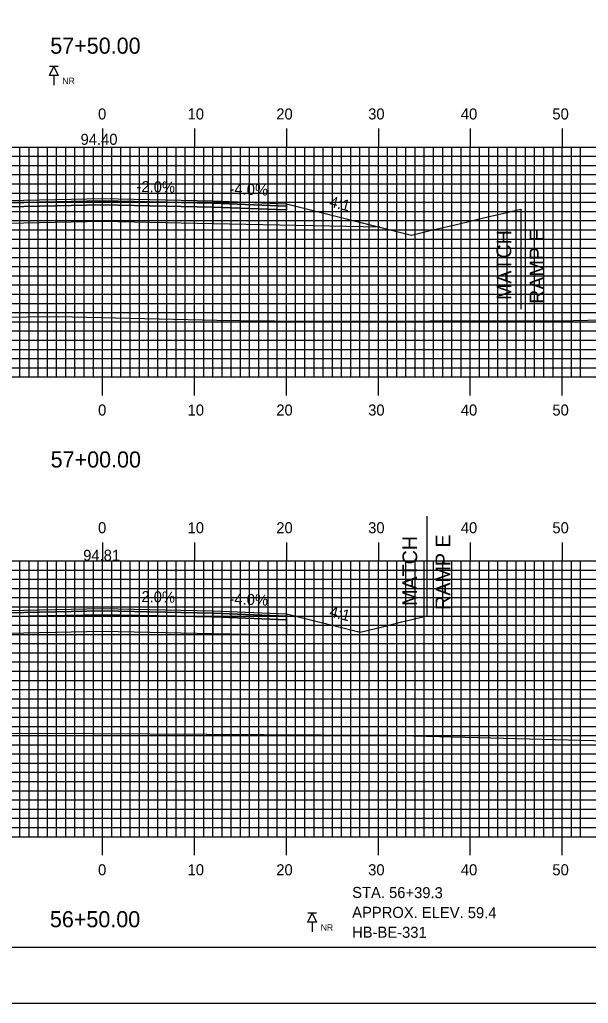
# Model space of a CAD drawing. Extents: x 1757069 to 1757412, y 442591 to 442811.
# Drawn here: x 1757225.6 to 1757287.4, y 442590.5 to 442697.5 of the extents above; entities that cross this region are included whole.
import ezdxf

# ---------------------------------------------------------------- set-up
doc = ezdxf.new("R2010")
doc.units = 0
for name, color, linetype in [('ANNOTATION', 7, 'Continuous'), ('BORDER', 7, 'Continuous'), ('BORING - NO REFUSAL', 7, 'Continuous'), ('D_Roadway_Centerline', 7, 'Continuous'), ('D_Roadway_Centerline_Text', 7, 'Continuous'), ('D_Roadway_Edge_Shoulder', 7, 'Continuous'), ('D_Roadway_Edge_TW', 7, 'Continuous'), ('D_Roadway_Pavement', 7, 'Continuous'), ('D_Roadway_SlopeLines', 7, 'Continuous'), ('D_Roadway_SubGrade', 7, 'Continuous'), ('H_V ANNOTATION', 7, 'Continuous'), ('MAJOR', 7, 'Continuous'), ('MINOR', 7, 'Continuous'), ('PLOT BOUNDARY', 7, 'Continuous'), ('S_Roadway_Centerline', 7, 'Continuous')]:
    doc.layers.add(name, color=color, linetype=linetype)

msp = doc.modelspace()

# ---------------------------------------------------------------- linework, layer by layer
at = {"layer": 'BORDER'}
msp.add_lwpolyline([(1757085, 442596.67), (1757405, 442596.67), (1757405, 442806.67), (1757085, 442806.67)], close=True, dxfattribs=at)
at = {"layer": 'BORING - NO REFUSAL'}
for p, q in [((1757229.78, 442692.42), (1757228.82, 442692.42)), ((1757229.3, 442691.46), (1757229.3, 442690.4)), ((1757257.88, 442600.35), (1757256.92, 442600.35)), ((1757257.4, 442599.39), (1757257.4, 442598.33))]:
    msp.add_line(p, q, dxfattribs=at)
for points in [[(1757229.3, 442692.42), (1757229.78, 442691.46), (1757228.82, 442691.46)], [(1757257.4, 442600.35), (1757257.88, 442599.39), (1757256.92, 442599.39)]]:
    msp.add_lwpolyline(points, close=True, dxfattribs=at)
at = {"layer": 'D_Roadway_Centerline'}
for points in [[(1757150.87, 442664.43), (1757178.46, 442673.58), (1757184.75, 442675.67), (1757187.19, 442676.48), (1757189.25, 442676.57), (1757189.96, 442676.6), (1757190.2, 442676.61), (1757193.88, 442676.78), (1757197.78, 442676.96), (1757197.9, 442676.96), (1757198.24, 442676.98), (1757200.33, 442677.07), (1757200.77, 442677.09), (1757206.86, 442677.37), (1757210.69, 442677.54), (1757212.29, 442677.62), (1757222.6, 442677.82), (1757234.6, 442678.06), (1757246.6, 442677.82), (1757254.6, 442677.5), (1757264.77, 442674.96), (1757268.22, 442674.1)], [(1757268.22, 442674.1), (1757270.53, 442674.65), (1757273.09, 442675.25), (1757274.59, 442675.61), (1757276.05, 442675.96), (1757278.57, 442676.55), (1757278.61, 442676.56), (1757278.62, 442676.56), (1757279.01, 442676.66), (1757280.11, 442676.92)], [(1757145.44, 442619.42), (1757182.82, 442631.81), (1757185.83, 442631.94), (1757187.53, 442632.02), (1757188.24, 442632.05), (1757193.86, 442632.31), (1757195.47, 442632.38), (1757196.4, 442632.42), (1757197.69, 442632.48), (1757201.15, 442632.63), (1757202.27, 442632.68), (1757203.92, 442632.76), (1757207.91, 442632.94), (1757222.6, 442633.23), (1757234.6, 442633.47), (1757246.6, 442633.23), (1757254.6, 442632.91), (1757262.62, 442630.91)], [(1757262.62, 442630.91), (1757265.21, 442631.54), (1757267.17, 442632.03), (1757267.79, 442632.18), (1757269.87, 442632.69)]]:
    msp.add_lwpolyline(points, dxfattribs=at)
at = {"layer": 'D_Roadway_Edge_Shoulder'}
for points in [[(1757246.6, 442677.82), (1757254.6, 442677.5), (1757254.6, 442677.25), (1757246.6, 442677.57)], [(1757246.6, 442633.23), (1757254.6, 442632.91), (1757254.6, 442632.66), (1757246.6, 442632.98)]]:
    msp.add_lwpolyline(points, close=True, dxfattribs=at)
at = {"layer": 'D_Roadway_Edge_TW'}
for points in [[(1757222.6, 442677.57), (1757222.6, 442677.82), (1757234.6, 442678.06), (1757246.6, 442677.82), (1757246.6, 442677.57), (1757234.6, 442677.81)], [(1757222.6, 442632.98), (1757222.6, 442633.23), (1757234.6, 442633.47), (1757246.6, 442633.23), (1757246.6, 442632.98), (1757234.6, 442633.22)]]:
    msp.add_lwpolyline(points, close=True, dxfattribs=at)
at = {"layer": 'D_Roadway_Pavement'}
for points in [[(1757222.6, 442677.15), (1757222.6, 442677.57), (1757234.6, 442677.81), (1757246.6, 442677.57), (1757246.6, 442677.15), (1757234.6, 442677.39)], [(1757246.6, 442677.57), (1757254.6, 442677.25), (1757254.6, 442676.83), (1757246.6, 442677.15)], [(1757222.6, 442632.57), (1757222.6, 442632.98), (1757234.6, 442633.22), (1757246.6, 442632.98), (1757246.6, 442632.57), (1757234.6, 442632.81)], [(1757246.6, 442632.98), (1757254.6, 442632.66), (1757254.6, 442632.25), (1757246.6, 442632.57)]]:
    msp.add_lwpolyline(points, close=True, dxfattribs=at)
at = {"layer": 'D_Roadway_SlopeLines'}
for points in [[(1757254.6, 442677.5), (1757268.22, 442674.1)], [(1757254.6, 442632.91), (1757262.62, 442630.91)]]:
    msp.add_lwpolyline(points, dxfattribs=at)
at = {"layer": 'D_Roadway_SubGrade'}
for p, q in [((1757280.11, 442676.92), (1757280.11, 442666.04)), ((1757269.87, 442643.52), (1757269.87, 442632.69))]:
    msp.add_line(p, q, dxfattribs=at)
for points in [[(1757222.6, 442675.32), (1757222.6, 442677.15), (1757234.6, 442677.39), (1757246.6, 442677.15), (1757246.6, 442675.32), (1757234.6, 442675.56)], [(1757246.6, 442677.15), (1757254.6, 442676.83), (1757254.6, 442677.25), (1757254.6, 442677.5), (1757264.77, 442674.96), (1757246.6, 442675.32)], [(1757222.6, 442630.73), (1757222.6, 442632.57), (1757234.6, 442632.81), (1757246.6, 442632.57), (1757246.6, 442630.73), (1757234.6, 442630.97)], [(1757246.6, 442632.57), (1757254.6, 442632.25), (1757254.6, 442632.66), (1757254.6, 442632.91), (1757254.6, 442630.57), (1757246.6, 442630.73)]]:
    msp.add_lwpolyline(points, close=True, dxfattribs=at)
at = {"layer": 'MAJOR'}
for p, q in [((1757234.6, 442685.67), (1757234.6, 442683.67)), ((1757244.6, 442685.67), (1757244.6, 442683.67)), ((1757254.6, 442685.67), (1757254.6, 442683.67)), ((1757264.6, 442685.67), (1757264.6, 442683.67)), ((1757274.6, 442685.67), (1757274.6, 442683.67)), ((1757284.6, 442685.67), (1757284.6, 442683.67)), ((1757094.6, 442683.67), (1757374.6, 442683.67)), ((1757094.6, 442683.67), (1757374.6, 442683.67)), ((1757234.6, 442658.67), (1757234.6, 442683.67)), ((1757244.6, 442658.67), (1757244.6, 442683.67)), ((1757254.6, 442658.67), (1757254.6, 442683.67)), ((1757264.6, 442658.67), (1757264.6, 442683.67)), ((1757274.6, 442658.67), (1757274.6, 442683.67)), ((1757284.6, 442658.67), (1757284.6, 442683.67)), ((1757094.6, 442678.67), (1757374.6, 442678.67)), ((1757094.6, 442673.67), (1757374.6, 442673.67)), ((1757094.6, 442668.67), (1757374.6, 442668.67)), ((1757094.6, 442663.67), (1757374.6, 442663.67)), ((1757094.6, 442658.67), (1757374.6, 442658.67)), ((1757094.6, 442658.67), (1757374.6, 442658.67)), ((1757234.6, 442656.66), (1757234.6, 442658.67)), ((1757244.6, 442656.66), (1757244.6, 442658.67)), ((1757254.6, 442656.66), (1757254.6, 442658.67)), ((1757264.6, 442656.66), (1757264.6, 442658.67)), ((1757274.6, 442656.66), (1757274.6, 442658.67)), ((1757284.6, 442656.66), (1757284.6, 442658.67)), ((1757234.6, 442640.67), (1757234.6, 442638.67)), ((1757244.6, 442640.67), (1757244.6, 442638.67)), ((1757254.6, 442640.67), (1757254.6, 442638.67)), ((1757264.6, 442640.67), (1757264.6, 442638.67)), ((1757274.6, 442640.67), (1757274.6, 442638.67)), ((1757284.6, 442640.67), (1757284.6, 442638.67)), ((1757094.6, 442638.67), (1757374.6, 442638.67)), ((1757094.6, 442638.67), (1757374.6, 442638.67)), ((1757234.6, 442608.67), (1757234.6, 442638.67)), ((1757244.6, 442608.67), (1757244.6, 442638.67)), ((1757254.6, 442608.67), (1757254.6, 442638.67)), ((1757264.6, 442608.67), (1757264.6, 442638.67)), ((1757274.6, 442608.67), (1757274.6, 442638.67)), ((1757284.6, 442608.67), (1757284.6, 442638.67)), ((1757094.6, 442633.67), (1757374.6, 442633.67)), ((1757094.6, 442628.67), (1757374.6, 442628.67)), ((1757094.6, 442623.67), (1757374.6, 442623.67)), ((1757094.6, 442618.67), (1757374.6, 442618.67)), ((1757094.6, 442613.67), (1757374.6, 442613.67)), ((1757094.6, 442608.67), (1757374.6, 442608.67)), ((1757094.6, 442608.67), (1757374.6, 442608.67)), ((1757234.6, 442606.66), (1757234.6, 442608.67)), ((1757244.6, 442606.66), (1757244.6, 442608.67)), ((1757254.6, 442606.66), (1757254.6, 442608.67)), ((1757264.6, 442606.66), (1757264.6, 442608.67)), ((1757274.6, 442606.66), (1757274.6, 442608.67)), ((1757284.6, 442606.66), (1757284.6, 442608.67))]:
    msp.add_line(p, q, dxfattribs=at)
at = {"layer": 'MINOR'}
for p, q in [((1757225.6, 442658.67), (1757225.6, 442683.67)), ((1757226.6, 442658.67), (1757226.6, 442683.67)), ((1757227.6, 442658.67), (1757227.6, 442683.67)), ((1757228.6, 442658.67), (1757228.6, 442683.67)), ((1757229.6, 442658.67), (1757229.6, 442683.67)), ((1757230.6, 442658.67), (1757230.6, 442683.67)), ((1757231.6, 442658.67), (1757231.6, 442683.67)), ((1757232.6, 442658.67), (1757232.6, 442683.67)), ((1757233.6, 442658.67), (1757233.6, 442683.67)), ((1757235.6, 442658.67), (1757235.6, 442683.67)), ((1757236.6, 442658.67), (1757236.6, 442683.67)), ((1757237.6, 442658.67), (1757237.6, 442683.67)), ((1757238.6, 442658.67), (1757238.6, 442683.67)), ((1757239.6, 442658.67), (1757239.6, 442683.67)), ((1757240.6, 442658.67), (1757240.6, 442683.67)), ((1757241.6, 442658.67), (1757241.6, 442683.67)), ((1757242.6, 442658.67), (1757242.6, 442683.67)), ((1757243.6, 442658.67), (1757243.6, 442683.67)), ((1757245.6, 442658.67), (1757245.6, 442683.67)), ((1757246.6, 442658.67), (1757246.6, 442683.67)), ((1757247.6, 442658.67), (1757247.6, 442683.67)), ((1757248.6, 442658.67), (1757248.6, 442683.67)), ((1757249.6, 442658.67), (1757249.6, 442683.67)), ((1757250.6, 442658.67), (1757250.6, 442683.67)), ((1757251.6, 442658.67), (1757251.6, 442683.67)), ((1757252.6, 442658.67), (1757252.6, 442683.67)), ((1757253.6, 442658.67), (1757253.6, 442683.67)), ((1757255.6, 442658.67), (1757255.6, 442683.67)), ((1757256.6, 442658.67), (1757256.6, 442683.67)), ((1757257.6, 442658.67), (1757257.6, 442683.67)), ((1757258.6, 442658.67), (1757258.6, 442683.67)), ((1757259.6, 442658.67), (1757259.6, 442683.67)), ((1757260.6, 442658.67), (1757260.6, 442683.67)), ((1757261.6, 442658.67), (1757261.6, 442683.67)), ((1757262.6, 442658.67), (1757262.6, 442683.67)), ((1757263.6, 442658.67), (1757263.6, 442683.67)), ((1757265.6, 442658.67), (1757265.6, 442683.67)), ((1757266.6, 442658.67), (1757266.6, 442683.67)), ((1757267.6, 442658.67), (1757267.6, 442683.67)), ((1757268.6, 442658.67), (1757268.6, 442683.67)), ((1757269.6, 442658.67), (1757269.6, 442683.67)), ((1757270.6, 442658.67), (1757270.6, 442683.67)), ((1757271.6, 442658.67), (1757271.6, 442683.67)), ((1757272.6, 442658.67), (1757272.6, 442683.67)), ((1757273.6, 442658.67), (1757273.6, 442683.67)), ((1757275.6, 442658.67), (1757275.6, 442683.67)), ((1757276.6, 442658.67), (1757276.6, 442683.67)), ((1757277.6, 442658.67), (1757277.6, 442683.67)), ((1757278.6, 442658.67), (1757278.6, 442683.67)), ((1757279.6, 442658.67), (1757279.6, 442683.67)), ((1757280.6, 442658.67), (1757280.6, 442683.67)), ((1757281.6, 442658.67), (1757281.6, 442683.67)), ((1757282.6, 442658.67), (1757282.6, 442683.67)), ((1757283.6, 442658.67), (1757283.6, 442683.67)), ((1757285.6, 442658.67), (1757285.6, 442683.67)), ((1757286.6, 442658.67), (1757286.6, 442683.67)), ((1757094.6, 442682.67), (1757374.6, 442682.67)), ((1757094.6, 442681.67), (1757374.6, 442681.67)), ((1757094.6, 442680.67), (1757374.6, 442680.67)), ((1757094.6, 442679.67), (1757374.6, 442679.67)), ((1757094.6, 442677.67), (1757374.6, 442677.67)), ((1757094.6, 442676.67), (1757374.6, 442676.67)), ((1757094.6, 442675.67), (1757374.6, 442675.67)), ((1757094.6, 442674.67), (1757374.6, 442674.67)), ((1757094.6, 442672.67), (1757374.6, 442672.67)), ((1757094.6, 442671.67), (1757374.6, 442671.67)), ((1757094.6, 442670.67), (1757374.6, 442670.67)), ((1757094.6, 442669.67), (1757374.6, 442669.67)), ((1757094.6, 442667.67), (1757374.6, 442667.67)), ((1757094.6, 442666.67), (1757374.6, 442666.67)), ((1757094.6, 442665.67), (1757374.6, 442665.67)), ((1757094.6, 442664.67), (1757374.6, 442664.67)), ((1757094.6, 442662.67), (1757374.6, 442662.67)), ((1757094.6, 442661.67), (1757374.6, 442661.67)), ((1757094.6, 442660.67), (1757374.6, 442660.67)), ((1757094.6, 442659.67), (1757374.6, 442659.67)), ((1757225.6, 442608.67), (1757225.6, 442638.67)), ((1757226.6, 442608.67), (1757226.6, 442638.67)), ((1757227.6, 442608.67), (1757227.6, 442638.67)), ((1757228.6, 442608.67), (1757228.6, 442638.67)), ((1757229.6, 442608.67), (1757229.6, 442638.67)), ((1757230.6, 442608.67), (1757230.6, 442638.67)), ((1757231.6, 442608.67), (1757231.6, 442638.67)), ((1757232.6, 442608.67), (1757232.6, 442638.67)), ((1757233.6, 442608.67), (1757233.6, 442638.67)), ((1757235.6, 442608.67), (1757235.6, 442638.67)), ((1757236.6, 442608.67), (1757236.6, 442638.67)), ((1757237.6, 442608.67), (1757237.6, 442638.67)), ((1757238.6, 442608.67), (1757238.6, 442638.67)), ((1757239.6, 442608.67), (1757239.6, 442638.67)), ((1757240.6, 442608.67), (1757240.6, 442638.67)), ((1757241.6, 442608.67), (1757241.6, 442638.67)), ((1757242.6, 442608.67), (1757242.6, 442638.67)), ((1757243.6, 442608.67), (1757243.6, 442638.67)), ((1757245.6, 442608.67), (1757245.6, 442638.67)), ((1757246.6, 442608.67), (1757246.6, 442638.67)), ((1757247.6, 442608.67), (1757247.6, 442638.67)), ((1757248.6, 442608.67), (1757248.6, 442638.67)), ((1757249.6, 442608.67), (1757249.6, 442638.67)), ((1757250.6, 442608.67), (1757250.6, 442638.67)), ((1757251.6, 442608.67), (1757251.6, 442638.67)), ((1757252.6, 442608.67), (1757252.6, 442638.67)), ((1757253.6, 442608.67), (1757253.6, 442638.67)), ((1757255.6, 442608.67), (1757255.6, 442638.67)), ((1757256.6, 442608.67), (1757256.6, 442638.67)), ((1757257.6, 442608.67), (1757257.6, 442638.67)), ((1757258.6, 442608.67), (1757258.6, 442638.67)), ((1757259.6, 442608.67), (1757259.6, 442638.67)), ((1757260.6, 442608.67), (1757260.6, 442638.67)), ((1757261.6, 442608.67), (1757261.6, 442638.67)), ((1757262.6, 442608.67), (1757262.6, 442638.67)), ((1757263.6, 442608.67), (1757263.6, 442638.67)), ((1757265.6, 442608.67), (1757265.6, 442638.67)), ((1757266.6, 442608.67), (1757266.6, 442638.67)), ((1757267.6, 442608.67), (1757267.6, 442638.67)), ((1757268.6, 442608.67), (1757268.6, 442638.67)), ((1757269.6, 442608.67), (1757269.6, 442638.67)), ((1757270.6, 442608.67), (1757270.6, 442638.67)), ((1757271.6, 442608.67), (1757271.6, 442638.67)), ((1757272.6, 442608.67), (1757272.6, 442638.67)), ((1757273.6, 442608.67), (1757273.6, 442638.67)), ((1757275.6, 442608.67), (1757275.6, 442638.67)), ((1757276.6, 442608.67), (1757276.6, 442638.67)), ((1757277.6, 442608.67), (1757277.6, 442638.67)), ((1757278.6, 442608.67), (1757278.6, 442638.67)), ((1757279.6, 442608.67), (1757279.6, 442638.67)), ((1757280.6, 442608.67), (1757280.6, 442638.67)), ((1757281.6, 442608.67), (1757281.6, 442638.67)), ((1757282.6, 442608.67), (1757282.6, 442638.67)), ((1757283.6, 442608.67), (1757283.6, 442638.67)), ((1757285.6, 442608.67), (1757285.6, 442638.67)), ((1757286.6, 442608.67), (1757286.6, 442638.67)), ((1757094.6, 442637.67), (1757374.6, 442637.67)), ((1757094.6, 442636.67), (1757374.6, 442636.67)), ((1757094.6, 442635.67), (1757374.6, 442635.67)), ((1757094.6, 442634.67), (1757374.6, 442634.67)), ((1757094.6, 442632.67), (1757374.6, 442632.67)), ((1757094.6, 442631.67), (1757374.6, 442631.67)), ((1757094.6, 442630.67), (1757374.6, 442630.67)), ((1757094.6, 442629.67), (1757374.6, 442629.67)), ((1757094.6, 442627.67), (1757374.6, 442627.67)), ((1757094.6, 442626.67), (1757374.6, 442626.67)), ((1757094.6, 442625.67), (1757374.6, 442625.67)), ((1757094.6, 442624.67), (1757374.6, 442624.67)), ((1757094.6, 442622.67), (1757374.6, 442622.67)), ((1757094.6, 442621.67), (1757374.6, 442621.67)), ((1757094.6, 442620.67), (1757374.6, 442620.67)), ((1757094.6, 442619.67), (1757374.6, 442619.67)), ((1757094.6, 442617.67), (1757374.6, 442617.67)), ((1757094.6, 442616.67), (1757374.6, 442616.67)), ((1757094.6, 442615.67), (1757374.6, 442615.67)), ((1757094.6, 442614.67), (1757374.6, 442614.67)), ((1757094.6, 442612.67), (1757374.6, 442612.67)), ((1757094.6, 442611.67), (1757374.6, 442611.67)), ((1757094.6, 442610.67), (1757374.6, 442610.67)), ((1757094.6, 442609.67), (1757374.6, 442609.67))]:
    msp.add_line(p, q, dxfattribs=at)
at = {"layer": 'PLOT BOUNDARY'}
msp.add_lwpolyline([(1757068.81, 442590.55), (1757408.81, 442590.55), (1757408.81, 442810.55), (1757068.81, 442810.55)], close=True, dxfattribs=at)
at = {"layer": 'S_Roadway_Centerline'}
for points in [[(1757094.6, 442664.18), (1757094.81, 442664.19), (1757104.62, 442664.24), (1757118.38, 442664.3), (1757139.82, 442664.37), (1757152.51, 442664.44), (1757175.36, 442664.55), (1757195.7, 442664.74), (1757219.61, 442665.15), (1757229.73, 442665.24), (1757247.02, 442664.86), (1757252.08, 442664.77), (1757253.32, 442664.76), (1757254.57, 442664.75), (1757285.8, 442664.81), (1757300.04, 442665.14), (1757329.94, 442665.38), (1757351.56, 442664.86), (1757374.6, 442664.54)], [(1757094.6, 442619.18), (1757096.35, 442619.19), (1757115.03, 442619.28), (1757138.2, 442619.39), (1757141.93, 442619.4), (1757145.49, 442619.42), (1757176.97, 442619.81), (1757201.32, 442619.7), (1757201.96, 442619.71), (1757202.39, 442619.71), (1757227.35, 442619.94), (1757258.33, 442619.75), (1757260.69, 442619.72), (1757265.63, 442619.7), (1757288.04, 442619.12), (1757304.62, 442618.87), (1757310.38, 442618.84), (1757330.15, 442618.65), (1757342.34, 442618.73), (1757360.53, 442618.93), (1757374.6, 442618.78)]]:
    msp.add_lwpolyline(points, dxfattribs=at)

# ---------------------------------------------------------------- texts
at = {"layer": 'ANNOTATION'}
for s, height, rotation, p in [('-2.0%', 1.2, 358.8542, (1757238.28, 442678.79)), ('-4.0%', 1.2, 357.7094, (1757248.39, 442678.55)), ('4:1', 1.2, 345.9638, (1757259.19, 442677.21)), ('MATCH', 1.6, 90, (1757279.06, 442667.03)), ('RAMP E', 1.6, 90, (1757282.66, 442666.61)), ('RAMP E', 1.6, 90, (1757272.42, 442633.34)), ('MATCH', 1.6, 90, (1757268.82, 442633.77)), ('-2.0%', 1.2, 358.8542, (1757238.28, 442634.2)), ('-4.0%', 1.2, 357.7094, (1757248.39, 442633.96)), ('4:1', 1.2, 345.9638, (1757259.19, 442632.63))]:
    msp.add_text(s, height=height, rotation=rotation, dxfattribs=at).set_placement(p)
at = {"layer": 'BORING - NO REFUSAL'}
for p in [(1757230.23, 442690.51), (1757258.33, 442598.44)]:
    msp.add_text('NR', height=0.7, dxfattribs=at).set_placement(p)
for s, p in [('STA. 56+39.3', (1757261.75, 442602.01)), ('APPROX. ELEV. 59.4', (1757261.75, 442599.85)), ('HB-BE-331', (1757261.74, 442597.69))]:
    msp.add_text(s, height=1.2, rotation=359.8142, dxfattribs=at).set_placement(p)
at = {"layer": 'D_Roadway_Centerline'}
for s, p in [('C', (1757234.59, 442678.06)), ('L', (1757234.6, 442678.05)), ('C', (1757234.59, 442633.47)), ('L', (1757234.6, 442633.47))]:
    msp.add_text(s, height=0.0146, dxfattribs=at).set_placement(p)
at = {"layer": 'D_Roadway_Centerline_Text'}
for s, p in [('94.40', (1757232.21, 442683.91)), ('94.81', (1757232.49, 442638.67))]:
    msp.add_text(s, height=1.2, dxfattribs=at).set_placement(p)
at = {"layer": 'H_V ANNOTATION'}
for s, height, p in [('57+50.00', 1.75, (1757228.91, 442693.82)), ('0', 1.2, (1757234.11, 442686.67)), ('10', 1.2, (1757243.85, 442686.67)), ('20', 1.2, (1757253.5, 442686.67)), ('30', 1.2, (1757263.49, 442686.67)), ('40', 1.2, (1757273.57, 442686.67)), ('50', 1.2, (1757283.53, 442686.67)), ('0', 1.2, (1757234.11, 442654.47)), ('10', 1.2, (1757243.85, 442654.47)), ('20', 1.2, (1757253.5, 442654.47)), ('30', 1.2, (1757263.49, 442654.47)), ('40', 1.2, (1757273.57, 442654.47)), ('50', 1.2, (1757283.53, 442654.47)), ('57+00.00', 1.75, (1757228.95, 442648.82)), ('0', 1.2, (1757234.11, 442641.67)), ('10', 1.2, (1757243.85, 442641.67)), ('20', 1.2, (1757253.5, 442641.67)), ('30', 1.2, (1757263.49, 442641.67)), ('40', 1.2, (1757273.57, 442641.67)), ('50', 1.2, (1757283.53, 442641.67)), ('0', 1.2, (1757234.11, 442604.47)), ('10', 1.2, (1757243.85, 442604.47)), ('20', 1.2, (1757253.5, 442604.47)), ('30', 1.2, (1757263.49, 442604.47)), ('40', 1.2, (1757273.57, 442604.47)), ('50', 1.2, (1757283.53, 442604.47)), ('56+50.00', 1.75, (1757228.87, 442598.82))]:
    msp.add_text(s, height=height, dxfattribs=at).set_placement(p)

doc.saveas('drawing.dxf')
